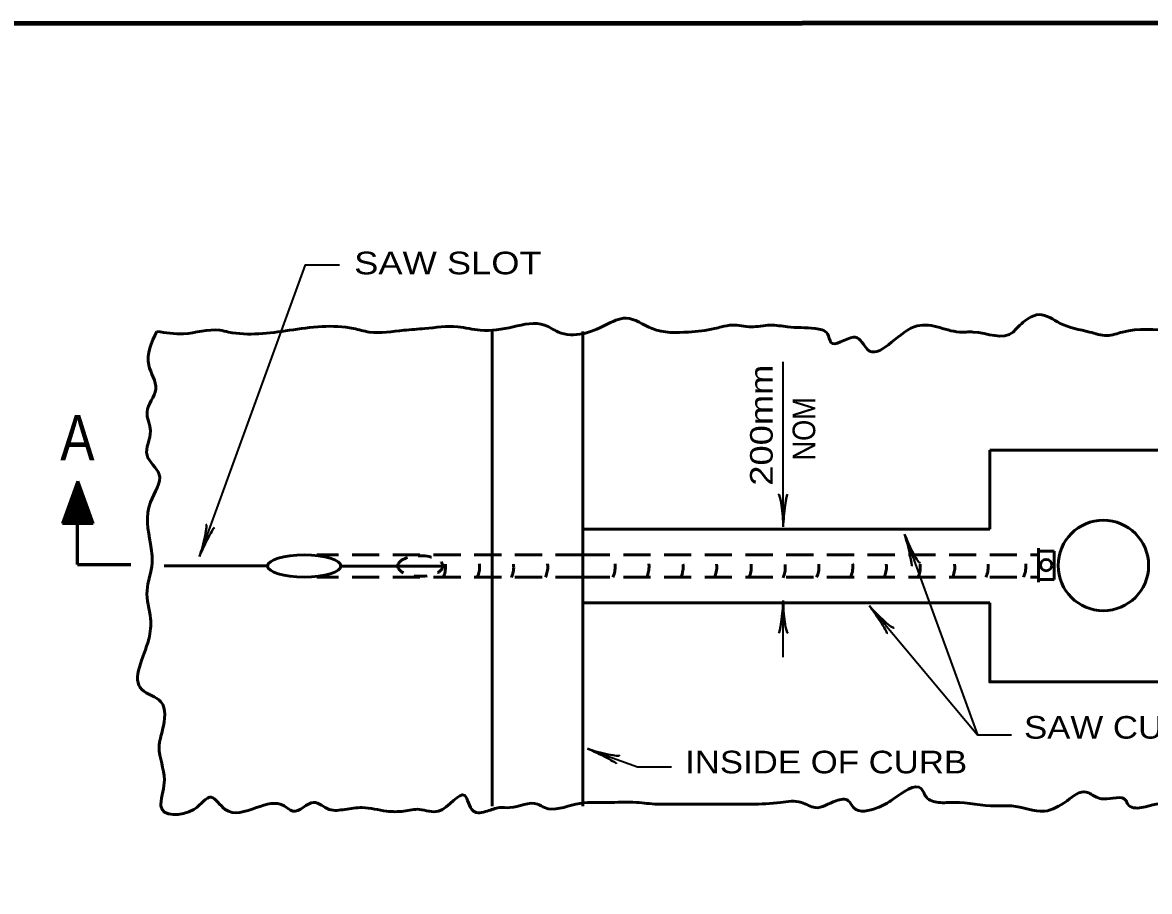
# Model space of a CAD drawing. Extents: x -90 to 623, y -379 to 75.
# Drawn here: x 108.4 to 208.1, y -7.4 to 69.4 of the extents above; entities that cross this region are included whole.
import ezdxf

# ---------------------------------------------------------------- set-up
doc = ezdxf.new("R2010")
doc.units = 0
doc.header["$LTSCALE"] = 0.8
doc.linetypes.add('MEDIUM_DASHED', pattern=[4.5, 3, -1.5])
doc.linetypes.add('SHORT_DASHED', pattern=[2.7, 1.5, -1.2])
doc.layers.add('1', color=7, linetype='Continuous', lineweight=35)

msp = doc.modelspace()

# ---------------------------------------------------------------- linework, layer by layer
at = {"layer": '1', "lineweight": 53}
for p, q in [((149.9592, 42.0949), (149.9592, 0.0949)), ((157.9592, 42.0949), (157.9592, 0.0949)), ((193.9592, 24.5949), (193.9592, 31.5949)), ((214.4592, 31.5949), (193.9592, 31.5949)), ((113.2923, 28.8522), (111.9243, 25.0935)), ((113.2923, 28.8522), (114.6604, 25.0935)), ((111.9243, 25.0935), (114.6604, 25.0935)), ((157.9592, 24.5949), (193.9592, 24.5949)), ((198.2224, 22.6517), (199.6428, 22.6517)), ((198.2608, 22.9204), (198.2608, 19.9204)), ((199.6428, 22.6517), (199.6428, 20.1517)), ((130.0465, 21.3519), (120.9388, 21.3519)), ((136.553, 21.3327), (145.593, 21.3327)), ((198.2224, 20.1517), (199.6428, 20.1517)), ((157.9592, 18.0949), (193.9592, 18.0949))]:
    msp.add_line(p, q, dxfattribs=at)
at = {"layer": '1'}
for p, q in [((175.6863, 24.8259), (175.6863, 39.4074)), ((186.4273, 24.1614), (192.8893, 6.4073)), ((175.6863, 13.2918), (175.6863, 18.2751))]:
    msp.add_line(p, q, dxfattribs=at)
at = {"layer": '1', "lineweight": 60}
for q in [(113.2712, 28.4673), (117.9854, 21.4673)]:
    msp.add_line((113.2712, 21.4673), q, dxfattribs=at)
at = {"layer": '1', "linetype": 'MEDIUM_DASHED', "lineweight": 53}
for p, q in [((157.9592, 22.3449), (134.4213, 22.3449)), ((157.9592, 22.3449), (198.2608, 22.3449)), ((157.9592, 20.3449), (134.4213, 20.3449)), ((157.9592, 20.3449), (198.2608, 20.3449))]:
    msp.add_line(p, q, dxfattribs=at)
at = {"layer": '1', "lineweight": 158}
msp.add_lwpolyline([(617.1938, 69.4188), (-42.5562, 69.3355), (-42.4728, -368.9978)], dxfattribs=at)
at = {"layer": '1'}
for points in [[(124.0472, 22.1841), (133.4392, 47.9881), (136.4392, 47.9881)], [(183.3132, 17.8196), (192.8893, 6.4073), (195.8893, 6.4073)], [(158.3773, 5.1835), (162.7943, 3.5757), (165.7943, 3.5757)]]:
    msp.add_lwpolyline(points, dxfattribs=at)
at = {"layer": '1', "lineweight": 53}
for points in [[(113.9141, 26.8705), (112.7241, 26.9281), (113.8373, 26.9857), (112.7241, 27.0433), (113.7605, 27.0624), (112.7817, 27.12), (113.7222, 27.1392), (112.8777, 27.216), (113.7222, 27.2543), (112.8008, 27.3119), (113.6646, 27.3695), (112.8968, 27.4079), (113.6837, 27.4271), (112.8777, 27.5231), (113.5686, 27.5231), (112.9544, 27.6191), (113.607, 27.6191), (113.012, 27.6958), (113.511, 27.7726), (113.0312, 27.7726), (113.4918, 27.8493), (113.1079, 27.9262), (113.4918, 27.9838), (113.0312, 27.8493), (113.4151, 28.0797), (113.0696, 28.0221), (113.4342, 28.1948), (113.1079, 28.1757), (113.3767, 28.2717), (113.2231, 28.3292), (113.3575, 28.406), (113.2039, 28.5212), (112.0331, 25.2007), (113.2615, 28.4636), (112.0907, 25.239), (113.2807, 28.3292), (112.2442, 25.2966), (113.012, 27.5998), (112.1099, 25.2966), (113.3575, 28.5019)], [(113.3575, 28.5019), (114.5475, 25.1623), (113.3575, 28.31), (114.4323, 25.3542), (113.4534, 27.811), (114.2403, 25.6229), (113.3383, 27.9262), (114.0868, 25.7957), (113.7222, 25.7381), (114.202, 25.5462), (112.3018, 25.4886), (112.321, 25.6037), (112.6281, 25.6229), (112.7625, 25.8916), (112.4937, 25.93), (114.5091, 25.2583), (114.0677, 25.8532), (112.7625, 25.8916), (112.6089, 26.0836), (112.0715, 25.2774), (112.8968, 27.1584)], [(112.0139, 25.1623), (114.5091, 25.1623), (114.4899, 25.2583), (112.0715, 25.239), (114.4131, 25.3158), (112.0715, 25.335), (114.3747, 25.3926), (112.1482, 25.4502), (114.3363, 25.5077), (112.2442, 25.4117), (114.4323, 25.4117), (114.2979, 25.6229), (112.1867, 25.5653), (114.2788, 25.6997), (112.2826, 25.6997), (114.1636, 25.834), (112.321, 25.8148), (114.2403, 25.9108), (112.3978, 25.9492), (114.1827, 26.026), (112.3978, 26.0643), (114.1636, 26.1028), (112.417, 26.1603), (114.0868, 26.1988), (112.417, 26.2371), (114.0677, 26.2563), (112.5513, 26.2947), (114.0484, 26.3522), (112.4937, 26.3522), (113.9717, 26.4674), (112.5129, 26.4291), (113.9525, 26.5442), (112.5129, 26.5058), (113.9717, 26.621), (112.5513, 26.6017), (113.9717, 26.7169), (112.5897, 26.6977), (113.9141, 26.7937), (112.6281, 26.8129), (113.9141, 26.8705)], [(193.9592, 18.0949), (193.9592, 11.0949), (214.4592, 11.0949)]]:
    msp.add_lwpolyline(points, dxfattribs=at)
for centre, radius in [((204.0092, 21.3921), 4), ((198.9517, 21.4233), 0.5)]:
    msp.add_circle(centre, radius, dxfattribs=at)
at = {"layer": '1', "linetype": 'SHORT_DASHED', "lineweight": 53}
for centre in [(143.6508, 21.2645), (146.6639, 21.2838), (149.6771, 21.2454), (152.6904, 21.2838), (158.6592, 21.2838), (161.6532, 21.2838), (164.6664, 21.2454), (167.6411, 21.2646), (170.6927, 21.2454), (173.7059, 21.2262), (176.6807, 21.2646), (179.6747, 21.2838), (182.6495, 21.2646), (185.6435, 21.2455), (188.6951, 21.2455), (191.6509, 21.2646), (194.9841, 21.2897)]:
    msp.add_arc(centre, 2.1707, 334.94384, 29.7373, dxfattribs=at)
at = {"layer": '1', "lineweight": 40}
for centre, major_axis, ratio, start_param, end_param in [((175.41, 25.9171), (0.1562, -1.7857), 0.122415, 0.8963533, 3.1415927), ((175.8979, 25.9464), (0.1757, 1.7565), 0.07063, 6.2823074, 8.5597026), ((124.1608, 23.304), (-0.464, -1.7314), 0.122415, 0.8963533, 3.1415927), ((124.6293, 23.1646), (0.7658, 1.5904), 0.07063, 6.2823074, 8.5597026), ((186.6117, 23.0361), (-0.4357, 1.7106), 0.07063, 3.1407148, 5.41811), ((186.6117, 23.0361), (-0.4357, 1.7106), 0.07063, 3.1407148, 5.41811), ((187.0602, 23.2305), (-0.7575, 1.6246), 0.122415, 0.8963533, 3.1415927), ((187.0602, 23.2305), (-0.7575, 1.6246), 0.122415, 0.8963533, 3.1415927), ((175.4747, 17.1546), (-0.1757, -1.7565), 0.07063, 6.2823074, 8.5597026), ((175.9626, 17.1839), (-0.1562, 1.7857), 0.122415, 0.8963533, 3.1415927), ((183.8713, 16.8252), (0.9945, -1.4584), 0.07063, 6.2823074, 8.5597026), ((184.2262, 17.1613), (-1.2674, 1.2675), 0.122415, 0.8963533, 3.1415927), ((159.3578, 4.6014), (1.5904, -0.7658), 0.07063, 6.2823074, 8.5597026), ((159.4971, 5.0699), (-1.7314, 0.464), 0.122415, 0.8963533, 3.1415927)]:
    msp.add_ellipse(centre, major_axis=major_axis, ratio=ratio, start_param=start_param, end_param=end_param, dxfattribs=at)
at = {"layer": '1', "lineweight": 53}
msp.add_ellipse((133.3222, 21.3449), major_axis=(-3.25, 0), ratio=0.300371, dxfattribs=at)
at = {"layer": '1', "linetype": 'SHORT_DASHED', "lineweight": 53}
msp.add_ellipse((143.5932, 21.3449), major_axis=(-2, 0), ratio=0.452986, dxfattribs=at)
at = {"layer": '1', "lineweight": 53}
for points in [[(120.2778, 42.0949), (122.6377, 41.8891), (125.8622, 42.1962), (126.6299, 42.0427), (132.0042, 42.1962), (137.6854, 42.3498), (139.0673, 42.0427), (142.1383, 42.1962), (143.9808, 42.3498), (146.8982, 42.5033), (148.8944, 42.1962), (151.8118, 42.5033), (154.5757, 42.6568), (155.8041, 42.0427), (157.9537, 41.8891), (159.9498, 42.6568), (161.7924, 43.2711), (164.0957, 42.3498), (167.3202, 42.0427), (169.6234, 42.3498), (170.2376, 42.5033), (171.1588, 42.6568), (172.8479, 42.5033), (174.5369, 42.6568), (176.0724, 42.5033), (178.5292, 42.3498), (179.604, 41.8891), (179.9111, 41.1214), (181.9073, 41.582), (182.0607, 41.582), (183.1356, 40.5072), (187.2814, 42.5033), (189.2775, 42.5033), (191.2737, 42.0427), (192.502, 42.0427), (196.0337, 42.0427), (196.1872, 42.1962), (197.4156, 43.2711), (198.3368, 43.5782), (200.1794, 42.8104), (202.7897, 42.0427), (204.3252, 41.7356), (205.7072, 42.0427), (210.0065, 42.1962), (210.6207, 42.1962), (213.0774, 42.8104), (214.1523, 42.8104)], [(214.1523, 42.8104), (214.92, 42.3498), (215.2272, 41.1214), (215.6877, 39.1253), (215.5342, 37.4363), (214.7665, 35.4401), (214.7665, 32.8298), (214.7665, 30.2195), (215.2272, 28.5304), (214.6129, 26.2272), (214.7665, 24.2311), (214.3058, 22.3885), (214.1523, 20.3924), (215.0736, 16.8608), (215.5342, 14.2505), (215.2272, 12.715), (213.9988, 10.7189), (214.6129, 8.4157), (215.8413, 6.4196), (214.6129, 3.6557), (214.3058, 0.7382), (213.9988, 0.1241), (211.542, -0.4901), (210.0065, -0.183), (209.6994, 0.1241), (207.3962, -0.0295), (206.1678, 0.2777), (206.0143, 0.5847), (204.0182, 0.7382), (203.4039, 0.8918), (202.4827, 1.3525), (200.7936, 0.5847), (198.7975, -0.3366), (195.8801, 0.1241), (194.4982, 0.1241), (190.813, 0.4312), (189.4311, 0.4312), (188.3562, 0.8918), (187.8956, 1.6596), (185.4388, 0.7382), (184.9782, 0.4312), (184.0569, -0.0295), (181.9073, -0.0295), (181.4466, 0.5847), (180.3717, 0.5847), (178.5292, -0.0295), (177.3007, 0.4312), (175.4582, 0.4312), (172.8479, 0.2777), (171.1588, 0.2777), (168.0879, 0.2777), (166.0917, 0.2777), (164.5563, 0.2777), (162.7138, 0.4312), (160.1034, 0.4312), (157.3396, 0.2777), (154.5757, -0.0295), (153.9615, 0.2777), (151.5048, -0.0295), (150.5834, -0.0295), (149.5086, -0.3366), (148.2802, -0.3366), (147.5125, 1.0453), (145.2092, -0.3366), (143.5203, -0.183), (142.1383, -0.3366), (140.6028, -0.3366), (138.4532, -0.0295), (136.9177, -0.183), (135.5358, -0.183), (134.1538, 0.4312), (132.3113, -0.3366), (131.5435, 0.1241), (129.0867, -0.0295), (126.3228, -0.183), (125.0945, 0.8918), (123.559, -0.183), (120.6416, 0.1241), (120.6416, 0.2777), (120.9487, 2.4273), (120.488, 5.3447), (120.7952, 6.8802), (120.6416, 9.3369), (118.9526, 10.4117), (119.5667, 14.8647), (119.7203, 16.7072), (119.4132, 19.164), (119.8738, 21.6208), (119.7203, 23.3098), (119.7203, 26.995), (120.488, 29.4518), (119.4132, 31.1408), (119.7203, 33.2904), (119.4132, 34.9795), (120.1809, 36.9756), (119.5667, 39.1253), (120.2778, 42.0949)]]:
    msp.add_spline(points, degree=3, dxfattribs=at)

# ---------------------------------------------------------------- texts
at = {"layer": '1'}
for s, height, width, p in [('SAW SLOT', 2, 1.2, (137.7387, 47.1477)), ('A', 4, 0.85, (111.742, 30.6989)), ('SAW CUT', 2, 1.15, (196.9911, 6.0724)), ('INSIDE OF CURB', 2, 1.15, (167.0108, 3.0036))]:
    msp.add_text(s, height=height, dxfattribs=dict(at, width=width)).set_placement(p)
for s, width, p in [('200mm', 1.2, (174.7576, 28.4495)), ('NOM', 0.9, (178.5199, 30.6727))]:
    msp.add_text(s, height=2, rotation=90, dxfattribs=dict(at, width=width)).set_placement(p)

doc.saveas('drawing.dxf')
